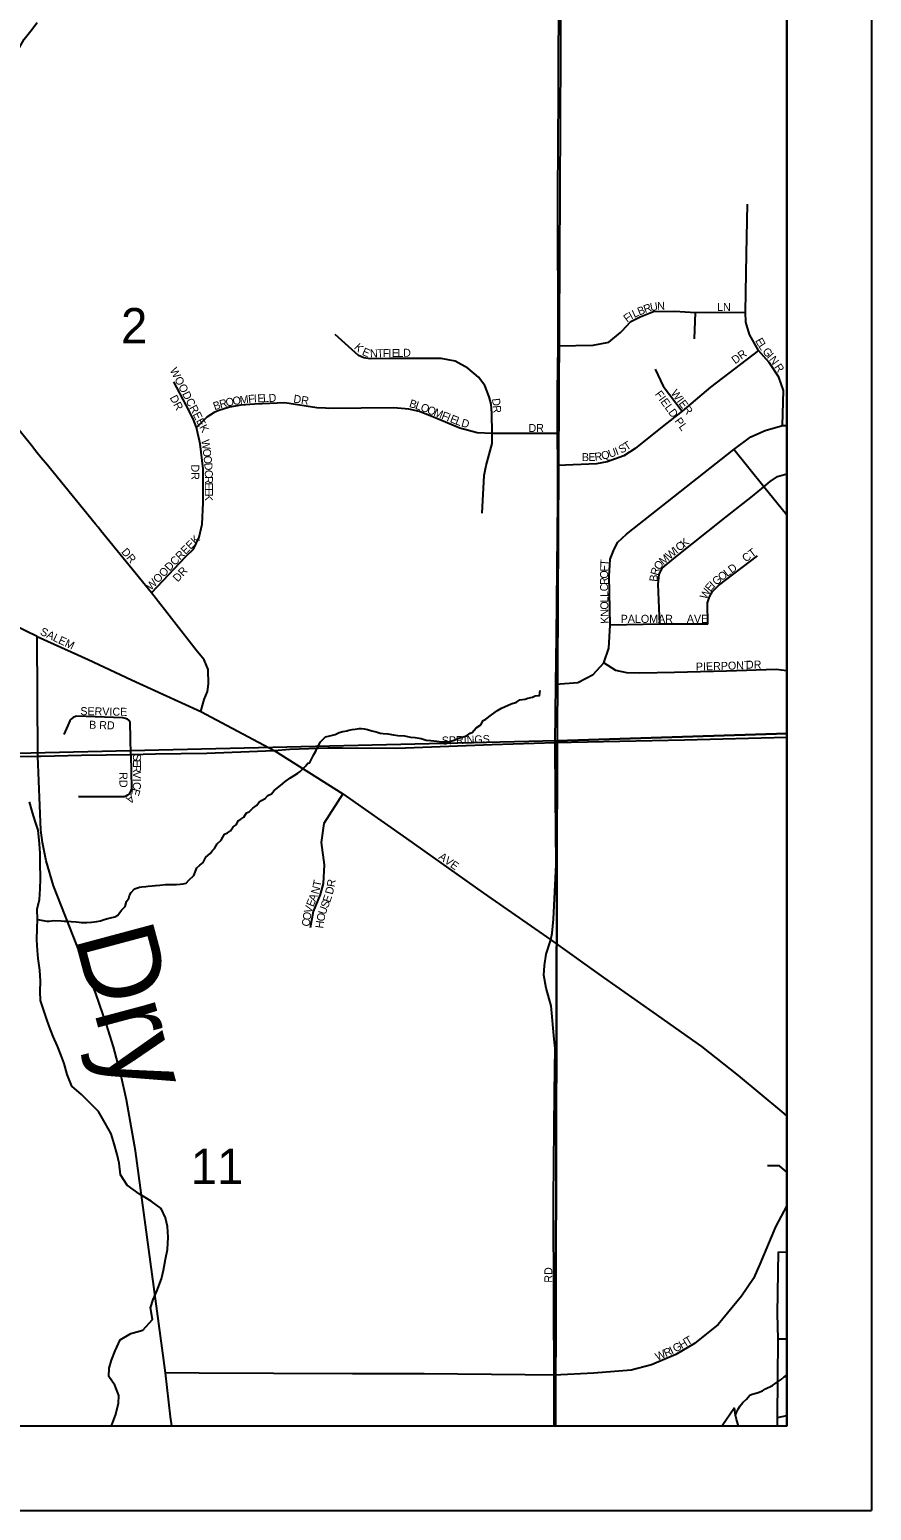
# Model space of a CAD drawing. Extents: x -209 to 4852, y 0 to 905.
# Drawn here: x 372.89 to 392.83, y 200.56 to 235.61 of the extents above; entities that cross this region are included whole.
import ezdxf

# ---------------------------------------------------------------- set-up
doc = ezdxf.new("R2010")
doc.units = 0
for name, color, linetype in [('Default', 7, 'Continuous'), ('GM_X_Airport_Location_Class_2', 7, 'Continuous'), ('GM_X_Airport_Location_Class_3', 7, 'Continuous'), ('GM_X_County_Road', 7, 'Continuous'), ('GM_X_County_Subdivision_Text', 7, 'Continuous'), ('GM_X_Major_River', 7, 'Continuous'), ('GM_X_Minor_River', 7, 'Continuous'), ('GM_X_Section_Text', 7, 'Continuous'), ('GM_X_Township_Road_Text', 7, 'Continuous'), ('GM_X_US_Location', 7, 'Continuous'), ('SH_Data', 7, 'Continuous')]:
    doc.layers.add(name, color=color, linetype=linetype)

msp = doc.modelspace()

# ---------------------------------------------------------------- linework, layer by layer
at = {"layer": 'Default'}
msp.add_lwpolyline([(390.832, 338.559), (254.832, 338.559), (254.832, 202.559), (390.832, 202.559)], close=True, dxfattribs=at)
at = {"layer": 'GM_X_Airport_Location_Class_2'}
for p, q in [((390.629, 206.678), (390.832, 206.672)), ((390.832, 204.61), (390.623, 204.61)), ((390.606, 202.76), (390.832, 202.801))]:
    msp.add_line(p, q, dxfattribs=at)
for points in [[(385.242, 214.061), (385.273, 214.222), (385.304, 214.556), (385.369, 215.845), (385.348, 217.473), (385.344, 218.733), (385.362, 220.119), (385.376, 221.245), (385.408, 224.469), (385.408, 225.291), (385.395, 226.051), (385.394, 227.041), (385.416, 228.123), (385.403, 231.675), (385.42, 234.107), (385.427, 236.85), (385.415, 238.265)], [(390.728, 226.237), (390.748, 227.07), (390.639, 227.385), (390.414, 227.726), (390.162, 228.014), (389.944, 228.388), (389.861, 228.684), (389.854, 228.922), (389.874, 230.304), (389.899, 231.474)], [(372.936, 225.761), (372.069, 226.827), (371.084, 228.02), (370.667, 228.508), (370.346, 228.851), (369.979, 229.216), (369.881, 229.325), (369.82, 229.397)], [(386.887, 228.443), (386.918, 228.47), (387.135, 228.697), (387.353, 228.812), (387.675, 228.935), (388.176, 228.941), (388.665, 228.915), (389.854, 228.922)], [(388.646, 228.292), (388.665, 228.915)], [(383.614, 224.162), (383.664, 225.058), (383.707, 225.293), (383.849, 225.814), (383.849, 226.049), (383.845, 226.528), (383.829, 226.743), (383.781, 226.914), (383.678, 227.187), (383.53, 227.38), (383.278, 227.598), (382.977, 227.76), (382.646, 227.827), (381.412, 227.821), (380.962, 227.814), (380.812, 227.838), (380.688, 227.891), (380.135, 228.388)], [(385.416, 228.123), (386.242, 228.143), (386.615, 228.211), (386.887, 228.443)], [(390.162, 228.014), (389.019, 227.149), (388.35, 226.581), (387.874, 226.208), (387.237, 225.694), (386.967, 225.517), (386.572, 225.379), (386.324, 225.334), (385.408, 225.291)], [(387.707, 227.571), (387.9, 227.166), (388.35, 226.581)], [(376.85, 226.194), (376.768, 226.395), (376.606, 226.719), (376.308, 227.272)], [(379.698, 226.654), (378.939, 226.773), (378.222, 226.744), (377.899, 226.719), (377.626, 226.669), (377.377, 226.594), (377.267, 226.542), (377.094, 226.436), (376.85, 226.194)], [(379.905, 226.646), (379.698, 226.654)], [(385.395, 226.051), (383.849, 226.049), (383.495, 226.065), (383.087, 226.178), (382.463, 226.435), (382.132, 226.57), (381.878, 226.628), (381.524, 226.654), (379.971, 226.644), (379.905, 226.646)], [(376.596, 223.138), (376.776, 223.312), (376.911, 223.598), (376.979, 223.901), (377.005, 224.41), (377.008, 225.215), (376.937, 225.802), (376.85, 226.194)], [(385.362, 220.119), (385.877, 220.153), (386.245, 220.343), (386.496, 220.618), (386.616, 220.966), (386.647, 221.513), (386.623, 222.669), (386.649, 223.077), (386.739, 223.308), (386.829, 223.475), (387.032, 223.664), (389.578, 225.668), (389.977, 225.967), (390.314, 226.121), (390.728, 226.237), (390.832, 226.237)], [(373.316, 225.297), (373.168, 225.473), (373.068, 225.598), (372.936, 225.761)], [(390.832, 224.114), (390.288, 224.79), (389.578, 225.668)], [(374.452, 223.906), (373.452, 225.136), (373.316, 225.297)], [(387.823, 221.538), (387.784, 222.479), (387.803, 222.71), (387.879, 222.863), (388.154, 223.093), (389.391, 224.077), (390.018, 224.562), (390.288, 224.79), (390.436, 224.913), (390.611, 225.032), (390.832, 225.093)], [(376.949, 219.468), (377.031, 219.753), (377.107, 219.942), (377.134, 220.124), (377.128, 220.464), (377.026, 220.692), (376.841, 220.922), (375.782, 222.274), (374.582, 223.743), (374.515, 223.829), (374.452, 223.906)], [(375.782, 222.274), (376.596, 223.138)], [(388.958, 221.533), (388.948, 222.042), (388.996, 222.183), (389.067, 222.305), (389.212, 222.454), (390.131, 223.154)], [(388.958, 221.533), (388.392, 221.538), (387.823, 221.538), (386.647, 221.513)], [(373.071, 221.241), (374.284, 220.698), (375.309, 220.216), (376.054, 219.877)], [(390.832, 220.431), (390.579, 220.463), (389.403, 220.42), (388.166, 220.393), (387.346, 220.373), (387.041, 220.381), (386.781, 220.442), (386.496, 220.618)], [(376.054, 219.877), (376.949, 219.468), (378.689, 218.549), (380.315, 217.518), (381.818, 216.46), (383.64, 215.177), (385.242, 214.061), (386.489, 213.174), (387.656, 212.351), (388.806, 211.538), (389.676, 210.851), (390.705, 209.997), (390.832, 209.888)], [(375.294, 218.454), (375.277, 219.217), (375.257, 219.249), (375.242, 219.265), (375.212, 219.286), (375.169, 219.303), (375.1, 219.319), (374.01, 219.355), (373.985, 219.35), (373.929, 219.323), (373.886, 219.292), (373.873, 219.281), (373.849, 219.248), (373.802, 219.14), (373.703, 218.921)], [(380.302, 218.605), (381.593, 218.599), (383.849, 218.688), (385.344, 218.733), (388.405, 218.797), (390.832, 218.857)], [(365.3, 218.232), (368.243, 218.307), (370.499, 218.366), (373.093, 218.411), (373.164, 218.412), (374.128, 218.431), (375.294, 218.454), (375.875, 218.465), (377.093, 218.481), (378.099, 218.524)], [(375.294, 218.454), (375.308, 217.652), (375.305, 217.626), (375.295, 217.598), (375.282, 217.571), (375.256, 217.522), (375.21, 217.487), (375.174, 217.464), (375.137, 217.447), (374.056, 217.452)], [(378.099, 218.524), (378.689, 218.549)], [(378.689, 218.549), (379.056, 218.574), (379.957, 218.607), (380.302, 218.605)], [(380.315, 217.518), (379.865, 216.818), (379.803, 216.368), (379.873, 215.84), (379.849, 215.399), (379.774, 215.135), (379.614, 214.735), (379.537, 214.349)], [(385.321, 211.714), (385.247, 212.498), (385.131, 212.916), (385.074, 213.226), (385.086, 213.454), (385.126, 213.727), (385.242, 214.061)], [(385.318, 202.559), (385.322, 202.795), (385.322, 203.762), (385.309, 205.412), (385.306, 207.934), (385.325, 210.444), (385.342, 211.5), (385.321, 211.714)], [(390.832, 208.563), (390.654, 208.715), (390.373, 208.714)], [(390.832, 207.776), (390.561, 207.267), (390.189, 206.383), (390.037, 206.044), (389.758, 205.626), (389.206, 204.956), (388.643, 204.512), (388.199, 204.245), (387.624, 204.002), (387.144, 203.877), (386.259, 203.805), (385.322, 203.762), (384.629, 203.768), (382.241, 203.788), (380.545, 203.791), (378.67, 203.801), (376.911, 203.805), (376.111, 203.814)], [(390.606, 202.559), (390.606, 202.76), (390.623, 204.61), (390.609, 205.218), (390.629, 206.678)]]:
    msp.add_lwpolyline(points, dxfattribs=at)
at = {"layer": 'GM_X_County_Road'}
for points in [[(372.499, 234.914), (372.617, 235.117), (372.767, 235.381), (372.923, 235.576), (373.071, 235.778)], [(381.103, 218.989), (381.194, 218.957), (381.269, 218.948), (381.383, 218.939), (381.512, 218.914), (381.618, 218.904), (381.777, 218.894), (381.913, 218.861), (382.027, 218.851), (382.171, 218.826), (382.291, 218.793), (382.397, 218.784), (382.541, 218.766), (382.655, 218.749), (382.731, 218.747), (382.799, 218.754), (382.868, 218.768), (382.952, 218.789), (383.059, 218.84), (383.135, 218.862), (383.242, 218.89), (383.327, 218.957), (383.38, 218.972), (383.474, 219.084), (383.581, 219.151), (383.636, 219.256), (383.697, 219.286), (383.836, 219.39), (383.975, 219.494), (384.074, 219.546), (384.304, 219.648), (384.426, 219.692), (384.503, 219.744), (384.572, 219.75), (384.633, 219.764), (384.694, 219.786), (384.808, 219.807), (384.869, 219.836), (384.968, 219.85), (384.986, 219.963)], [(373.081, 214.544), (373.306, 214.507), (373.359, 214.506), (373.466, 214.519), (373.64, 214.516), (373.716, 214.507), (373.807, 214.505), (373.883, 214.496), (373.997, 214.487), (374.065, 214.485), (374.126, 214.477), (374.247, 214.475), (374.361, 214.48), (374.422, 214.487), (374.49, 214.501), (374.574, 214.514), (374.658, 214.543), (374.75, 214.565), (374.811, 214.586), (374.91, 214.607), (374.987, 214.644), (375.072, 214.764), (375.157, 214.854), (375.19, 214.968), (375.245, 215.051), (375.261, 215.111), (375.3, 215.187), (375.378, 215.269), (375.5, 215.313), (375.553, 215.319), (375.645, 215.325), (375.705, 215.332), (375.797, 215.338), (375.873, 215.352), (375.979, 215.357), (376.116, 215.37), (376.177, 215.377), (376.367, 215.373), (376.458, 215.379), (376.534, 215.393), (376.603, 215.407), (376.665, 215.475), (376.781, 215.587), (376.852, 215.768), (376.929, 215.828), (377.007, 215.895), (377.07, 216.023), (377.17, 216.105), (377.224, 216.18), (377.278, 216.225), (377.334, 216.338), (377.434, 216.42), (377.512, 216.564), (377.581, 216.6), (377.651, 216.645), (377.713, 216.735), (377.79, 216.787), (377.845, 216.885), (377.899, 216.922), (377.968, 216.967), (378.031, 217.072), (378.092, 217.094), (378.184, 217.183), (378.269, 217.243), (378.331, 217.325), (378.385, 217.363), (378.477, 217.407), (378.539, 217.482), (378.623, 217.518), (378.686, 217.601), (378.801, 217.683), (378.886, 217.757), (378.94, 217.802), (379.056, 217.891), (379.163, 217.95), (379.248, 218.01), (379.301, 218.047), (379.441, 218.181), (379.48, 218.234), (379.533, 218.263), (379.565, 218.324), (379.628, 218.452), (379.675, 218.527), (379.699, 218.595), (379.746, 218.671), (379.777, 218.739), (379.901, 218.866), (380.008, 218.895), (380.13, 218.923), (380.23, 218.974), (380.314, 218.996), (380.405, 219.009), (380.458, 219.024), (380.535, 219.045), (380.603, 219.051), (380.702, 219.065), (380.755, 219.064), (380.816, 219.055), (380.899, 219.046), (380.997, 219.014), (381.103, 218.989)], [(374.329, 210.2), (374.121, 210.402), (373.897, 210.597), (373.781, 210.873), (373.71, 211.134), (373.646, 211.325), (373.559, 211.548), (373.45, 211.779), (373.356, 212.024), (373.284, 212.224), (373.227, 212.415), (373.156, 212.63), (373.145, 212.844), (373.15, 213.087), (373.14, 213.346), (373.1, 213.621), (373.081, 213.812), (373.064, 214.064), (373.077, 214.338), (373.081, 214.544), (373.071, 214.787), (373.128, 215.015), (373.149, 215.273), (373.154, 215.51), (373.146, 215.891), (373.143, 216.111), (373.132, 216.333), (373.094, 216.661), (373.03, 216.875), (372.965, 217.075), (372.894, 217.327)], [(374.836, 202.559), (374.931, 202.814), (374.997, 203.087), (375.009, 203.277), (374.915, 203.523), (374.768, 203.731), (374.779, 203.922), (374.836, 204.118), (374.924, 204.338), (375.036, 204.594), (375.29, 204.749), (375.58, 204.828), (375.805, 205.075), (375.758, 205.35), (375.823, 205.554), (375.91, 205.751), (376.015, 206.038), (376.064, 206.243), (376.115, 206.508), (376.158, 206.736), (376.179, 207.025), (376.161, 207.277), (376.113, 207.484), (376.011, 207.707), (375.771, 207.879), (375.486, 208.052), (375.209, 208.255), (375.047, 208.502), (375.015, 208.777), (374.966, 208.984), (374.895, 209.237), (374.824, 209.474), (374.684, 209.721), (374.53, 209.998), (374.329, 210.2)], [(389.617, 202.814), (389.639, 202.876), (389.687, 202.967), (389.726, 203.035), (389.788, 203.11), (389.873, 203.192), (389.951, 203.289), (390.012, 203.311), (390.073, 203.325), (390.149, 203.347), (390.256, 203.391), (390.326, 203.435), (390.486, 203.516), (390.579, 203.575), (390.694, 203.657), (390.764, 203.724), (390.832, 203.762)]]:
    msp.add_lwpolyline(points, dxfattribs=at)
at = {"layer": 'GM_X_County_Subdivision_Text'}
for points in [[(373.071, 221.241), (371.654, 221.932), (370.666, 222.527), (370.318, 222.797)], [(376.111, 203.814), (375.401, 209.067), (375.193, 210.275), (375.059, 210.873), (374.881, 211.532), (374.72, 212.058), (374.461, 212.792), (374.012, 213.938), (373.461, 215.341), (373.291, 215.935), (373.201, 216.367), (373.159, 216.657), (373.093, 218.411), (373.071, 221.241)], [(376.261, 202.559), (376.233, 202.775), (376.111, 203.814)]]:
    msp.add_lwpolyline(points, dxfattribs=at)
at = {"layer": 'GM_X_Major_River'}
msp.add_line((389.586, 202.983), (389.295, 202.559), dxfattribs=at)
for points in [[(389.617, 202.814), (389.586, 202.983)], [(389.682, 202.559), (389.636, 202.71), (389.617, 202.814)]]:
    msp.add_lwpolyline(points, dxfattribs=at)
at = {"layer": 'GM_X_Minor_River'}
for points in [[(365.444, 238.341), (366.505, 238.365), (385.487, 238.317), (385.389, 218.776), (365.169, 218.303)], [(390.832, 218.947), (390.832, 238.271), (386.645, 238.294), (385.487, 238.317), (385.389, 218.776)], [(364.947, 202.559), (385.353, 202.559), (385.389, 218.776), (365.169, 218.303)], [(385.353, 202.559), (390.832, 202.559), (390.832, 218.947), (385.389, 218.776)]]:
    msp.add_lwpolyline(points, close=True, dxfattribs=at)
at = {"layer": 'GM_X_US_Location'}
msp.add_lwpolyline([(285.96, 202.559), (390.832, 202.559), (390.832, 238.067), (286.607, 238.38), (286.27, 219.835)], close=True, dxfattribs=at)
at = {"layer": 'SH_Data'}
for p, q in [((392.832, 340.559), (392.832, 200.559)), ((390.832, 338.559), (390.832, 202.559)), ((254.832, 202.559), (390.832, 202.559)), ((252.832, 200.559), (392.832, 200.559))]:
    msp.add_line(p, q, dxfattribs=at)

# ---------------------------------------------------------------- texts
at = {"layer": 'GM_X_Airport_Location_Class_3'}
for s, height, rotation, p in [('F', 0.189, 36.7988, (387.047, 228.669)), ('I', 0.189, 28.5407, (387.147, 228.745)), ('L', 0.189, 25.4774, (387.218, 228.783)), ('B', 0.189, 21.585, (387.335, 228.839)), ('R', 0.189, 19.8711, (387.473, 228.894)), ('U', 0.189, 9.9079, (387.606, 228.943)), ('N', 0.189, 3.1713, (387.764, 228.971)), ('LN', 0.1894, 0, (389.177, 228.95)), ('K', 0.189, 315.7264, (380.569, 228.072)), ('E', 0.189, 298.6672, (390.075, 228.248)), ('L', 0.189, 303.2164, (390.148, 228.117)), ('E', 0.189, 337.408, (380.752, 227.914)), ('N', 0.189, 1.8487, (380.96, 227.847)), ('T', 0.189, 0.9016, (381.126, 227.853)), ('F', 0.189, 0.9726, (381.259, 227.855)), ('I', 0.189, 0.9835, (381.393, 227.857)), ('E', 0.189, 0.9562, (381.476, 227.858)), ('L', 0.189, 0.9562, (381.609, 227.861)), ('D', 0.189, 0.9618, (381.743, 227.863)), ('DR', 0.1894, 36.2589, (389.606, 227.683)), ('G', 0.189, 310.8749, (390.238, 227.983)), ('I', 0.189, 310.9367, (390.347, 227.857)), ('N', 0.189, 306.6251, (390.399, 227.797)), ('WOODCREEK', 0.1894, 297.4271, (376.209, 227.549)), ('R', 0.189, 303.4005, (390.525, 227.624)), ('DR', 0.1894, 297.8914, (376.207, 226.897)), ('B', 0.189, 18.819, (377.278, 226.597)), ('R', 0.189, 15.0081, (377.417, 226.644)), ('O', 0.189, 12.4031, (377.56, 226.683)), ('O', 0.189, 9.9725, (377.72, 226.718)), ('M', 0.189, 6.479, (377.882, 226.747)), ('F', 0.189, 5.0336, (378.079, 226.769)), ('I', 0.189, 3.3228, (378.21, 226.781)), ('E', 0.189, 1.8036, (378.292, 226.785)), ('L', 0.189, 1.6943, (378.425, 226.79)), ('D', 0.189, 1.6947, (378.559, 226.794)), ('DR', 0.1894, 351.0327, (379.133, 226.783)), ('B', 0.189, 342.5402, (381.871, 226.682)), ('L', 0.189, 341.7983, (382.014, 226.637)), ('D', 0.189, 276.7699, (383.845, 226.871)), ('FIELD PL', 0.1894, 306.098, (387.696, 226.979)), ('WIER', 0.1894, 306.8699, (388.072, 227.003)), ('O', 0.189, 339.0833, (382.138, 226.597)), ('O', 0.189, 338.4259, (382.293, 226.537)), ('M', 0.189, 338.4185, (382.448, 226.476)), ('F', 0.189, 338.4345, (382.634, 226.402)), ('I', 0.189, 338.4259, (382.758, 226.353)), ('E', 0.189, 338.4015, (382.836, 226.323)), ('L', 0.189, 339.4085, (382.963, 226.272)), ('R', 0.189, 274.7899, (383.864, 226.707)), ('D', 0.189, 344.5172, (383.105, 226.22)), ('DR', 0.1894, 0, (384.711, 226.084)), ('W', 0.189, 278.3679, (376.962, 225.891)), ('I', 0.189, 20.869, (386.801, 225.528)), ('S', 0.189, 28.8827, (386.905, 225.569)), ('T', 0.189, 32.2364, (387.032, 225.64)), ('O', 0.189, 276.5936, (376.993, 225.678)), ('O', 0.189, 276.4392, (377.012, 225.513)), ('B', 0.189, 0.1457, (385.977, 225.395)), ('E', 0.189, 0.8115, (386.13, 225.396)), ('R', 0.189, 7.3424, (386.287, 225.399)), ('Q', 0.189, 14.6956, (386.461, 225.424)), ('U', 0.189, 19.2108, (386.638, 225.471)), ('DR', 0.1894, 270, (376.724, 225.315)), ('D', 0.189, 274.7255, (377.031, 225.349)), ('C', 0.189, 270.7286, (377.044, 225.186)), ('R', 0.189, 270, (377.046, 225.037)), ('E', 0.189, 269.9956, (377.046, 224.887)), ('E', 0.189, 269.9956, (377.046, 224.753)), ('K', 0.189, 269.9928, (377.046, 224.62)), ('WOODCREEK', 0.1894, 45.9089, (375.768, 222.323)), ('DR', 0.1894, 310.5949, (375.054, 223.238)), ('W', 0.189, 39.416, (388.054, 223.056)), ('I', 0.189, 39.4357, (388.221, 223.194)), ('C', 0.189, 39.4497, (388.286, 223.247)), ('K', 0.189, 39.4278, (388.402, 223.342)), ('CT', 0.1894, 36.2494, (389.856, 222.994)), ('F', 0.189, 87.7596, (386.596, 222.778)), ('T', 0.189, 87.7039, (386.601, 222.911)), ('O', 0.189, 52.7192, (387.809, 222.802)), ('M', 0.189, 40.6941, (387.903, 222.927)), ('D', 0.189, 36.8828, (389.525, 222.728)), ('DR', 0.1894, 47.1199, (376.404, 222.52)), ('O', 0.189, 88.8197, (386.593, 222.612)), ('R', 0.189, 90.7286, (386.595, 222.464)), ('B', 0.189, 83.1611, (387.758, 222.533)), ('R', 0.189, 73.3008, (387.774, 222.674)), ('G', 0.189, 39.4586, (389.158, 222.443)), ('O', 0.189, 37.1409, (389.285, 222.548)), ('L', 0.189, 36.859, (389.418, 222.648)), ('C', 0.189, 90.8371, (386.597, 222.314)), ('L', 0.189, 90.847, (386.599, 222.181)), ('W', 0.189, 63.0064, (388.926, 222.107)), ('E', 0.189, 49.4283, (389.017, 222.29)), ('I', 0.189, 43.5787, (389.101, 222.388)), ('O', 0.189, 90.8379, (386.603, 221.881)), ('L', 0.189, 90.847, (386.601, 222.048)), ('N', 0.189, 90.8306, (386.606, 221.714)), ('K', 0.189, 90.8525, (386.608, 221.548)), ('PALOMAR', 0.1894, 0, (386.894, 221.567)), ('AVE', 0.1894, 0, (388.461, 221.567)), ('SALEM', 0.1894, 334.5361, (373.126, 221.297)), ('PIERPONT', 0.1894, 1.7084, (388.677, 220.434)), ('DR', 0.1894, 0, (389.861, 220.484)), ('SERVICE', 0.1894, 359.0128, (374.095, 219.384)), ('B RD', 0.1894, 358.2112, (374.302, 219.062)), ('SPRINGS', 0.1894, 2.0123, (382.659, 218.684)), ('S', 0.189, 269.6175, (375.346, 218.465)), ('RD', 0.1894, 270, (375.024, 218.032)), ('R', 0.189, 269.6021, (375.344, 218.199)), ('V', 0.189, 269.5987, (375.343, 218.049)), ('E', 0.189, 269.5902, (375.345, 218.332)), ('C', 0.189, 269.6114, (375.342, 217.799)), ('I', 0.189, 269.6085, (375.342, 217.882)), ('A', 0.189, 213.0596, (375.302, 217.518)), ('E', 0.189, 254.0621, (375.343, 217.662)), ('AVE', 0.1894, 324.6895, (382.565, 215.994)), ('N', 0.189, 73.8455, (379.733, 215.129)), ('T', 0.189, 78.9796, (379.784, 215.307)), ('D', 0.189, 75.9264, (380.072, 215.124)), ('R', 0.189, 80.7228, (380.116, 215.303)), ('V', 0.189, 73.2589, (379.568, 214.676)), ('E', 0.189, 68.0717, (379.614, 214.831)), ('A', 0.189, 68.1106, (379.664, 214.955)), ('U', 0.189, 71.337, (379.902, 214.645)), ('S', 0.189, 67.9602, (379.954, 214.8)), ('E', 0.189, 70.0466, (380.007, 214.931)), ('C', 0.189, 82.0313, (379.525, 214.369)), ('O', 0.189, 81.9533, (379.546, 214.518)), ('H', 0.189, 81.9533, (379.848, 214.325)), ('O', 0.189, 78.6472, (379.871, 214.488)), ('RD', 0.1894, 90, (385.275, 205.948)), ('T', 0.189, 30.7342, (388.483, 204.462)), ('W', 0.189, 23.8344, (387.763, 204.098)), ('R', 0.189, 23.8396, (387.961, 204.185)), ('I', 0.189, 25.9944, (388.105, 204.249)), ('G', 0.189, 29.7519, (388.192, 204.292)), ('H', 0.189, 30.7481, (388.34, 204.376))]:
    msp.add_text(s, height=height, rotation=rotation, dxfattribs=at).set_placement(p)
at = {"layer": 'GM_X_Section_Text'}
msp.add_text('Dry', height=1.8959, rotation=284.9746, dxfattribs=at).set_placement((373.94, 214.143))
at = {"layer": 'GM_X_Township_Road_Text'}
for s, height, p in [('2', 0.837, (375.061, 228.181)), ('11', 0.8371, (376.711, 208.283))]:
    msp.add_text(s, height=height, rotation=0, dxfattribs=at).set_placement(p)

doc.saveas('drawing.dxf')
